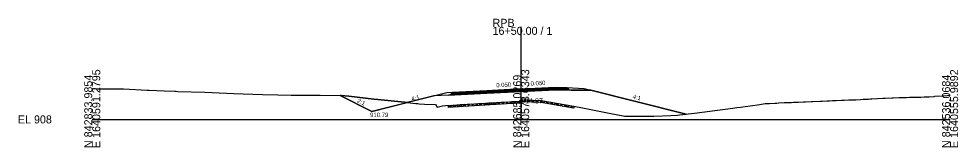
# Model space of a CAD drawing. Extents: x -26 to 1641030, y -10 to 842962.
# Drawn here: x -25.7 to 302.8, y 6490.3 to 6535.1 of the extents above; entities that cross this region are included whole.
import ezdxf

# ---------------------------------------------------------------- set-up
doc = ezdxf.new("R2010")
doc.units = 0
for name, color, linetype in [('Exist Cross Section Cell', 7, 'Continuous'), ('Exist XS Center Line Elevation Label', 7, 'Continuous'), ('Exist XS Ground Line', 7, 'Continuous'), ('Prop CMT Pvmt Course 1', 7, 'Continuous'), ('Prop CMT Pvmt Course 2', 7, 'Continuous'), ('Prop CMT Pvmt Course 3', 7, 'Continuous'), ('Prop CMT Pvmt Surface', 7, 'Continuous'), ('Prop CMT Pvmt Surface Shoulder', 7, 'Continuous'), ('Prop CMT Shld Paved Course 1', 7, 'Continuous'), ('Prop CMT Shld Paved Course 2', 7, 'Continuous'), ('Prop CMT Shld Paved Course 3', 7, 'Continuous'), ('Prop CMT Slope Grass', 7, 'Continuous'), ('Prop CMT Subgrade Earthwork', 7, 'Continuous'), ('Prop XS Ditch Standard Text', 7, 'Continuous'), ('Prop XS SE Text', 7, 'Continuous'), ('Prop XS Side Slope Text', 7, 'Continuous'), ('Prop XS Undercut Exc', 7, 'Continuous'), ('Scratch_Level_2', 7, 'Continuous'), ('Scratch_Level_3', 7, 'Continuous')]:
    doc.layers.add(name, color=color, linetype=linetype)

msp = doc.modelspace()

# ---------------------------------------------------------------- linework, layer by layer
at = {"layer": 'Exist Cross Section Cell'}
for p, q in [((150, 6500), (150, 6532.32)), ((0, 6500), (150, 6500)), ((150, 6500), (300, 6500))]:
    msp.add_line(p, q, dxfattribs=at)
at = {"layer": 'Exist XS Ground Line'}
for p, q in [((0, 6510.77), (1.87, 6510.68)), ((1.87, 6510.68), (9.19, 6510.66)), ((9.19, 6510.66), (10.88, 6510.62)), ((10.88, 6510.62), (19.26, 6510.24)), ((19.26, 6510.24), (19.88, 6510.22)), ((19.88, 6510.22), (25.16, 6510)), ((25.16, 6510), (28.89, 6509.83)), ((28.89, 6509.83), (29.33, 6509.82)), ((29.33, 6509.82), (29.89, 6509.8)), ((29.89, 6509.8), (39.4, 6509.56)), ((39.4, 6509.56), (46.89, 6509.14)), ((46.89, 6509.14), (49.47, 6509.08)), ((49.47, 6509.08), (52.73, 6508.93)), ((52.73, 6508.93), (59.54, 6508.64)), ((59.54, 6508.64), (64.9, 6508.59)), ((64.9, 6508.59), (69.61, 6508.44)), ((69.61, 6508.44), (75.58, 6508.47)), ((75.58, 6508.47), (79.68, 6508.51)), ((79.68, 6508.51), (87.01, 6508.3)), ((87.01, 6508.3), (89.75, 6508.11)), ((294.72, 6508.16), (297.35, 6508.24)), ((297.35, 6508.24), (297.78, 6508.26)), ((297.78, 6508.26), (300, 6508.41)), ((89.75, 6508.11), (98.43, 6507.08)), ((98.43, 6507.08), (99.82, 6506.96)), ((99.82, 6506.96), (109.14, 6505.97)), ((109.14, 6505.97), (113.18, 6505.55)), ((113.18, 6505.55), (113.86, 6505.51)), ((113.86, 6505.51), (114.27, 6505.49)), ((114.27, 6505.49), (116.15, 6505.38)), ((116.15, 6505.38), (120.04, 6505.16)), ((120.04, 6505.16), (120.59, 6504.25)), ((123.59, 6504.8), (126.11, 6504.99)), ((126.11, 6504.99), (127.76, 6505.11)), ((127.76, 6505.11), (128.74, 6505.18)), ((128.74, 6505.18), (131.15, 6505.32)), ((131.15, 6505.32), (131.6, 6505.35)), ((131.6, 6505.35), (133.66, 6505.47)), ((133.66, 6505.47), (135.05, 6505.54)), ((135.05, 6505.54), (135.39, 6505.56)), ((135.39, 6505.56), (136.18, 6505.61)), ((136.18, 6505.61), (137.54, 6505.69)), ((137.54, 6505.69), (138.7, 6505.76)), ((138.7, 6505.76), (140.17, 6505.84)), ((140.17, 6505.84), (141.22, 6505.91)), ((141.22, 6505.91), (143.02, 6506)), ((143.02, 6506), (143.73, 6506.04)), ((143.73, 6506.04), (145.88, 6506.16)), ((145.88, 6506.16), (146.25, 6506.18)), ((146.25, 6506.18), (146.69, 6506.2)), ((146.69, 6506.2), (147.26, 6506.22)), ((147.26, 6506.22), (148.41, 6506.26)), ((148.41, 6506.26), (149.38, 6506.29)), ((149.38, 6506.29), (149.88, 6506.87)), ((149.88, 6506.87), (150.7, 6506.84)), ((150.7, 6506.84), (157.03, 6506.58)), ((157.03, 6506.58), (165.7, 6505.05)), ((165.7, 6505.05), (170.31, 6504.24)), ((226.7, 6504.32), (233.49, 6505.25)), ((233.49, 6505.25), (235.33, 6505.51)), ((235.33, 6505.51), (235.63, 6505.53)), ((235.63, 6505.53), (236.88, 6505.61)), ((236.88, 6505.61), (238.83, 6505.68)), ((238.83, 6505.68), (239.4, 6505.7)), ((239.4, 6505.7), (240.12, 6505.75)), ((240.12, 6505.75), (241.92, 6505.86)), ((241.92, 6505.86), (242.98, 6505.9)), ((242.98, 6505.9), (244.59, 6505.96)), ((244.59, 6505.96), (245.21, 6505.99)), ((245.21, 6505.99), (246.36, 6506.03)), ((246.36, 6506.03), (246.95, 6506.06)), ((246.95, 6506.06), (248.69, 6506.13)), ((248.69, 6506.13), (249.47, 6506.16)), ((249.47, 6506.16), (251.54, 6506.23)), ((251.54, 6506.23), (251.98, 6506.25)), ((251.98, 6506.25), (254.58, 6506.34)), ((254.58, 6506.34), (255.28, 6506.38)), ((255.28, 6506.38), (257.06, 6506.47)), ((257.06, 6506.47), (257.77, 6506.5)), ((257.77, 6506.5), (258.91, 6506.55)), ((258.91, 6506.55), (259.54, 6506.58)), ((259.54, 6506.58), (260.11, 6506.6)), ((260.11, 6506.6), (262.05, 6506.68)), ((262.05, 6506.68), (262.97, 6506.72)), ((262.97, 6506.72), (264.57, 6506.8)), ((264.57, 6506.8), (265.82, 6506.84)), ((265.82, 6506.84), (267.09, 6506.89)), ((267.09, 6506.89), (268.68, 6506.98)), ((268.68, 6506.98), (269.61, 6507.02)), ((269.61, 6507.02), (270.03, 6507.04)), ((270.03, 6507.04), (271.45, 6507.12)), ((271.45, 6507.12), (272.12, 6507.16)), ((272.12, 6507.16), (272.59, 6507.19)), ((272.59, 6507.19), (274.64, 6507.28)), ((274.64, 6507.28), (276.53, 6507.37)), ((276.53, 6507.37), (277.24, 6507.41)), ((277.24, 6507.41), (279.68, 6507.51)), ((279.68, 6507.51), (280.1, 6507.53)), ((280.1, 6507.53), (282.19, 6507.61)), ((282.19, 6507.61), (282.67, 6507.62)), ((282.67, 6507.62), (283.03, 6507.63)), ((283.03, 6507.63), (283.37, 6507.64)), ((283.37, 6507.64), (284.71, 6507.68)), ((284.71, 6507.68), (285.81, 6507.71)), ((285.81, 6507.71), (287.23, 6507.75)), ((287.23, 6507.75), (288.35, 6507.78)), ((288.35, 6507.78), (289.75, 6507.82)), ((289.75, 6507.82), (290.93, 6507.85)), ((290.93, 6507.85), (291.74, 6507.87)), ((291.74, 6507.87), (292.64, 6507.91)), ((292.64, 6507.91), (294.41, 6508)), ((294.41, 6508), (294.72, 6508.16)), ((120.59, 6504.25), (122.48, 6504.69)), ((122.48, 6504.69), (123.59, 6504.8)), ((170.31, 6504.24), (180.8, 6502.21)), ((180.8, 6502.21), (186.23, 6501.14)), ((205.33, 6501.58), (210.66, 6502.16)), ((210.66, 6502.16), (224.05, 6503.96)), ((224.05, 6503.96), (225.45, 6504.13)), ((225.45, 6504.13), (226.7, 6504.32)), ((186.23, 6501.14), (189.01, 6501.12)), ((189.01, 6501.12), (192.57, 6501.15)), ((192.57, 6501.15), (194.48, 6501.15)), ((194.48, 6501.15), (195.15, 6501.16)), ((195.15, 6501.16), (196.38, 6501.16)), ((196.38, 6501.16), (202.3, 6501.41)), ((202.3, 6501.41), (204.62, 6501.5)), ((204.62, 6501.5), (205.33, 6501.58))]:
    msp.add_line(p, q, dxfattribs=at)
at = {"layer": 'Prop CMT Pvmt Course 1'}
for points in [[(150, 6510.63), (138.01, 6510.03)], [(138.01, 6509.78), (150, 6510.38)], [(138.01, 6510.03), (138.01, 6509.78)], [(150, 6510.63), (162.01, 6511.23)], [(162.01, 6510.98), (150, 6510.38)], [(150, 6510.38), (150, 6510.63)], [(150, 6510.38), (150, 6510.63)], [(162.01, 6511.23), (162.01, 6510.98)]]:
    msp.add_lwpolyline(points, dxfattribs=at)
msp.add_lwpolyline([(150, 6510.38), (150, 6510.5), (150, 6510.5), (150, 6510.38)], close=True, dxfattribs=at)
msp.add_lwpolyline([(150, 6510.38), (150, 6510.5), (150, 6510.5), (150, 6510.38)], close=True, dxfattribs=at)
at = {"layer": 'Prop CMT Pvmt Course 2'}
for p in [(138.01, 6509.44), (162.01, 6510.64)]:
    msp.add_line(p, (150, 6510.04), dxfattribs=at)
for points in [[(150, 6510.38), (138.01, 6509.78)], [(138.01, 6509.78), (138.01, 6509.44)], [(150, 6510.38), (162.01, 6510.98)], [(150, 6510.13), (150, 6510.38)], [(150, 6510.13), (150, 6510.38)], [(162.01, 6510.98), (162.01, 6510.64)]]:
    msp.add_lwpolyline(points, dxfattribs=at)
at = {"layer": 'Prop CMT Pvmt Course 3'}
for p, q in [((150, 6510.04), (138.01, 6509.44)), ((138.01, 6509.11), (150, 6509.71)), ((150, 6510.04), (162.01, 6510.64)), ((162.01, 6510.31), (150, 6509.71))]:
    msp.add_line(p, q, dxfattribs=at)
for points in [[(138.01, 6509.44), (138.01, 6509.11)], [(150, 6509.75), (150, 6510.13)], [(150, 6509.75), (150, 6510.13)], [(162.01, 6510.64), (162.01, 6510.31)]]:
    msp.add_lwpolyline(points, dxfattribs=at)
at = {"layer": 'Prop CMT Pvmt Surface'}
for points in [[(150, 6510.63), (138.01, 6510.03)], [(150, 6510.63), (162.01, 6511.23)]]:
    msp.add_lwpolyline(points, dxfattribs=at)
at = {"layer": 'Prop CMT Pvmt Surface Shoulder'}
for points in [[(138.01, 6510.03), (126.01, 6509.43)], [(162.01, 6511.23), (166.01, 6511.19)]]:
    msp.add_lwpolyline(points, dxfattribs=at)
at = {"layer": 'Prop CMT Shld Paved Course 1'}
for points in [[(138.01, 6510.03), (126.01, 6509.43), (125.74, 6509.16)], [(125.74, 6509.16), (138.01, 6509.78)], [(138.01, 6509.78), (138.01, 6510.03)], [(162.01, 6511.23), (166.01, 6511.19), (166.26, 6510.93)], [(162.01, 6510.98), (162.01, 6511.23)], [(166.26, 6510.93), (162.01, 6510.98)]]:
    msp.add_lwpolyline(points, dxfattribs=at)
at = {"layer": 'Prop CMT Shld Paved Course 2'}
for p, q in [((125.39, 6508.81), (138.01, 6509.44)), ((125.74, 6509.16), (125.39, 6508.81)), ((138.01, 6509.78), (125.74, 6509.16)), ((162.01, 6510.98), (166.26, 6510.93)), ((166.6, 6510.6), (162.01, 6510.64)), ((166.26, 6510.93), (166.6, 6510.6))]:
    msp.add_line(p, q, dxfattribs=at)
for points in [[(138.01, 6509.53), (138.01, 6509.78)], [(162.01, 6510.64), (162.01, 6510.98)]]:
    msp.add_lwpolyline(points, dxfattribs=at)
at = {"layer": 'Prop CMT Shld Paved Course 3'}
for p, q in [((124.54, 6508.44), (138.01, 6509.11)), ((125.39, 6508.81), (125.04, 6508.46)), ((138.01, 6509.44), (125.48, 6508.82)), ((162.01, 6510.64), (166.51, 6510.6)), ((167.43, 6510.26), (162.01, 6510.31)), ((166.6, 6510.6), (166.93, 6510.26))]:
    msp.add_line(p, q, dxfattribs=at)
for points in [[(138.01, 6509.15), (138.01, 6509.44)], [(162.01, 6510.31), (162.01, 6510.64)]]:
    msp.add_lwpolyline(points, dxfattribs=at)
at = {"layer": 'Prop CMT Slope Grass'}
msp.add_line((126.01, 6509.43), (124.01, 6509.33), dxfattribs=at)
for points in [[(97.78, 6502.77), (86.7, 6508.31)], [(124.01, 6509.33), (97.78, 6502.77)], [(166.01, 6511.19), (172.01, 6510.77), (207.71, 6501.84)]]:
    msp.add_lwpolyline(points, dxfattribs=at)
at = {"layer": 'Prop CMT Subgrade Earthwork'}
for p, q in [((124.54, 6508.44), (119.43, 6508.18)), ((138.01, 6509.11), (124.54, 6508.44)), ((150, 6509.71), (138.01, 6509.11)), ((150, 6509.71), (162.01, 6510.31)), ((162.01, 6510.31), (167.43, 6510.26)), ((167.43, 6510.26), (174.32, 6510.19))]:
    msp.add_line(p, q, dxfattribs=at)
at = {"layer": 'Prop XS Undercut Exc'}
for p, q in [((124.55, 6504.87), (131.6, 6505.35)), ((125.17, 6504.25), (125.89, 6504.96)), ((126.01, 6504.97), (126.63, 6504.35)), ((126.69, 6504.36), (127.4, 6505.07)), ((127.34, 6505.06), (127.96, 6504.44)), ((128.21, 6504.45), (128.92, 6505.17)), ((128.66, 6505.15), (129.29, 6504.52)), ((129.72, 6504.55), (130.43, 6505.27)), ((129.99, 6505.24), (130.62, 6504.61)), ((131.23, 6504.65), (131.95, 6505.37)), ((131.31, 6505.33), (131.95, 6504.7)), ((131.6, 6505.35), (146.25, 6506.18)), ((146.72, 6505.53), (131.64, 6504.68)), ((132.65, 6505.41), (133.28, 6504.77)), ((132.73, 6504.74), (133.45, 6505.45)), ((133.99, 6505.48), (134.62, 6504.85)), ((134.23, 6504.82), (134.95, 6505.54)), ((135.33, 6505.56), (135.96, 6504.92)), ((135.73, 6504.91), (136.44, 6505.62)), ((136.66, 6505.63), (137.3, 6505)), ((137.23, 6504.99), (137.94, 6505.71)), ((138, 6505.71), (138.64, 6505.07)), ((138.73, 6505.08), (139.44, 6505.79)), ((139.34, 6505.79), (139.98, 6505.15)), ((140.23, 6505.16), (140.94, 6505.88)), ((140.68, 6505.86), (141.32, 6505.22)), ((141.73, 6505.25), (142.44, 6505.96)), ((142.02, 6505.94), (142.66, 6505.3)), ((143.23, 6505.33), (143.94, 6506.05)), ((143.36, 6506.01), (143.99, 6505.38)), ((144.69, 6506.09), (145.33, 6505.45)), ((144.72, 6505.42), (145.44, 6506.13)), ((146.03, 6506.17), (146.67, 6505.53)), ((146.22, 6505.5), (146.92, 6506.2)), ((146.25, 6506.18), (149.38, 6506.29)), ((147.29, 6505.56), (146.72, 6505.53)), ((149.4, 6505.62), (147.29, 6505.56)), ((147.39, 6506.22), (148.03, 6505.58)), ((147.7, 6505.57), (148.39, 6506.26)), ((148.76, 6506.27), (149.4, 6505.62)), ((149.17, 6505.61), (150.4, 6506.85)), ((149.38, 6506.29), (149.88, 6506.87)), ((150.67, 6506.17), (149.4, 6505.62)), ((149.74, 6506.7), (150.39, 6506.05)), ((149.88, 6506.87), (157.03, 6506.58)), ((157.01, 6505.91), (150.67, 6506.17)), ((151.03, 6506.83), (151.73, 6506.13)), ((151.12, 6506.15), (151.76, 6506.8)), ((152.48, 6506.1), (153.12, 6506.74)), ((152.5, 6506.77), (153.2, 6506.07)), ((153.83, 6506.04), (154.48, 6506.68)), ((153.98, 6506.7), (154.68, 6506)), ((155.19, 6505.98), (155.83, 6506.63)), ((155.46, 6506.64), (156.15, 6505.94)), ((156.55, 6505.93), (157.17, 6506.55)), ((156.93, 6506.58), (157.73, 6505.78)), ((165.58, 6504.39), (157.01, 6505.91)), ((157.03, 6506.58), (165.7, 6505.05)), ((157.8, 6505.77), (158.38, 6506.34)), ((158.63, 6506.29), (159.45, 6505.47)), ((159, 6505.55), (159.58, 6506.13)), ((160.2, 6505.34), (160.78, 6505.92)), ((160.35, 6505.99), (161.17, 6505.17)), ((161.41, 6505.13), (161.98, 6505.7)), ((162.07, 6505.69), (162.89, 6504.86)), ((162.61, 6504.91), (163.18, 6505.49)), ((163.78, 6505.38), (164.61, 6504.56)), ((163.81, 6504.7), (164.39, 6505.28)), ((165.01, 6504.49), (165.59, 6505.07)), ((165.5, 6505.08), (166.33, 6504.26)), ((165.7, 6505.05), (168.46, 6504.57)), ((124.55, 6504.2), (124.55, 6504.87)), ((126.16, 6504.32), (124.55, 6504.2)), ((124.69, 6504.88), (125.31, 6504.26)), ((131.64, 6504.68), (126.16, 6504.32)), ((168.47, 6503.88), (165.58, 6504.39)), ((166.21, 6504.28), (166.79, 6504.86)), ((167.21, 6504.78), (168.04, 6503.96)), ((167.42, 6504.07), (168, 6504.65)), ((168.46, 6504.57), (168.47, 6503.88))]:
    msp.add_line(p, q, dxfattribs=at)
at = {"layer": 'Scratch_Level_2'}
for p, q in [((86.7, 6508.31), (97.78, 6502.77)), ((97.78, 6502.77), (110.16, 6505.86)), ((110.16, 6505.86), (109.14, 6505.97))]:
    msp.add_line(p, q, dxfattribs=at)
msp.add_lwpolyline([(109.14, 6505.97), (99.82, 6506.96), (98.43, 6507.08), (89.75, 6508.11), (87.01, 6508.3), (86.7, 6508.31)], dxfattribs=at)
at = {"layer": 'Scratch_Level_3'}
for p, q in [((124.54, 6508.44), (119.43, 6508.18)), ((138.01, 6509.11), (124.54, 6508.44)), ((150, 6509.71), (138.01, 6509.11)), ((162.01, 6510.31), (150, 6509.71)), ((167.43, 6510.26), (162.01, 6510.31)), ((174.32, 6510.19), (167.43, 6510.26)), ((207.71, 6501.84), (174.32, 6510.19)), ((119.43, 6508.18), (110.16, 6505.86)), ((110.16, 6505.86), (113.18, 6505.55))]:
    msp.add_line(p, q, dxfattribs=at)
msp.add_lwpolyline([(113.18, 6505.55), (113.86, 6505.51), (114.27, 6505.49), (116.15, 6505.38), (120.04, 6505.16), (120.59, 6504.25), (122.48, 6504.69), (123.59, 6504.8), (126.11, 6504.99), (127.76, 6505.11), (128.74, 6505.18), (131.15, 6505.32), (131.6, 6505.35), (133.66, 6505.47), (135.05, 6505.54), (135.39, 6505.56), (136.18, 6505.61), (137.54, 6505.69), (138.7, 6505.76), (140.17, 6505.84), (141.22, 6505.91), (143.02, 6506), (143.73, 6506.04), (145.88, 6506.16), (146.25, 6506.18), (146.69, 6506.2), (147.26, 6506.22), (148.41, 6506.26), (149.38, 6506.29), (149.88, 6506.87), (150.7, 6506.84), (157.03, 6506.58), (165.7, 6505.05), (170.31, 6504.24), (180.8, 6502.21), (186.23, 6501.14), (189.01, 6501.12), (192.57, 6501.15), (194.48, 6501.15), (195.15, 6501.16), (196.38, 6501.16), (202.3, 6501.41), (204.62, 6501.5), (205.33, 6501.58), (207.71, 6501.84)], dxfattribs=at)

# ---------------------------------------------------------------- texts
at = {"layer": 'Exist Cross Section Cell'}
for s, p in [('RPB', (140, 6532.32)), ('16+50.00 / 1', (140, 6529.52)), ('EL 908', (-26, 6498.6))]:
    msp.add_text(s, height=2.8, dxfattribs=at).set_placement(p)
for s, p in [('N 842833.9854', (0, 6490)), ('E 1640591.2795', (2.8, 6490)), ('N 842685.0269', (150, 6490)), ('E 1640573.6343', (152.8, 6490)), ('N 842536.0684', (300, 6490)), ('E 1640555.9892', (302.8, 6490))]:
    msp.add_text(s, height=2.8, rotation=90, dxfattribs=at).set_placement(p)
at = {"layer": 'Exist XS Center Line Elevation Label'}
msp.add_text('914.87', height=1.8, dxfattribs=at).set_placement((150, 6505.57))
at = {"layer": 'Prop XS Ditch Standard Text'}
msp.add_text('910.79', height=1.5, dxfattribs=at).set_placement((97.18, 6500.85))
at = {"layer": 'Prop XS SE Text'}
for p in [(141.33, 6511.19), (153.33, 6511.79)]:
    msp.add_text('0.050', height=1.5, rotation=2.8624, dxfattribs=at).set_placement(p)
at = {"layer": 'Prop XS Side Slope Text'}
for s, rotation, p in [('4:1', 14.0362, (111.82, 6506.41)), ('4:1', 345.9638, (188.89, 6507.32)), ('2:1', 333.4349, (92.44, 6506.02))]:
    msp.add_text(s, height=1.5, rotation=rotation, dxfattribs=at).set_placement(p)

doc.saveas('drawing.dxf')
